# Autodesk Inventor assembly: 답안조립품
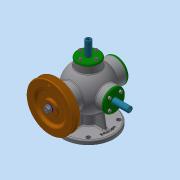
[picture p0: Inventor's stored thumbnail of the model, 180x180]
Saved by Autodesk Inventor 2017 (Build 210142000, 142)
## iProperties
Part Number: 답안조립품
Material: 일반
Document SubType Name: Assembly
Designer: MRC
Author: MRC
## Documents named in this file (17)
- C:\Users\MRC\Desktop\600911V1002\답안조립품.iam
- C:\Users\MRC\Desktop\600911V1002\본체.ipt
- C:\Users\MRC\Desktop\600911V1002\Ű 4x4.ipt
- C:\Users\MRC\Desktop\600911V1002\V-벨트풀리.ipt
- C:\Users\MRC\Desktop\600911V1002\너트 M8x1.ipt
- C:\Users\MRC\Desktop\600911V1002\뒤커버.ipt
- C:\Users\MRC\Desktop\600911V1002\베어링 6202.ipt
- C:\Users\MRC\Desktop\600911V1002\본체커버.ipt
- C:\Users\MRC\Desktop\600911V1002\볼트 M4.ipt
- C:\Users\MRC\Desktop\600911V1002\스프링1.ipt
- C:\Users\MRC\Desktop\600911V1002\스프링2.ipt
- C:\Users\MRC\Desktop\600911V1002\슬라이드 커버.ipt
- C:\Users\MRC\Desktop\600911V1002\슬라이드.ipt
- C:\Users\MRC\Desktop\600911V1002\앞커버.ipt
- C:\Users\MRC\Desktop\600911V1002\오일 실.ipt
- C:\Users\MRC\Desktop\600911V1002\와셔 8x17.ipt
- C:\Users\MRC\Desktop\600911V1002\축.ipt
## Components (1 placed, 1 different names)
1. V-벨트풀리:1
